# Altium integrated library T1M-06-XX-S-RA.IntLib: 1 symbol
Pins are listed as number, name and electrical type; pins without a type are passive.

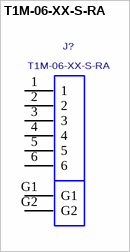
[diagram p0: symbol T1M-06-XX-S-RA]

## T1M-06-XX-S-RA
designator J?
1MM TERMINAL STRIP, 6 PINS.; MANUFACTURER: SAMTEC
footprint T1M-06-XX-S-RA
pins: 1, 2, 3, 4, 5, 6, G1, G2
